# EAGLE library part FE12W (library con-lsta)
FEMALE HEADER
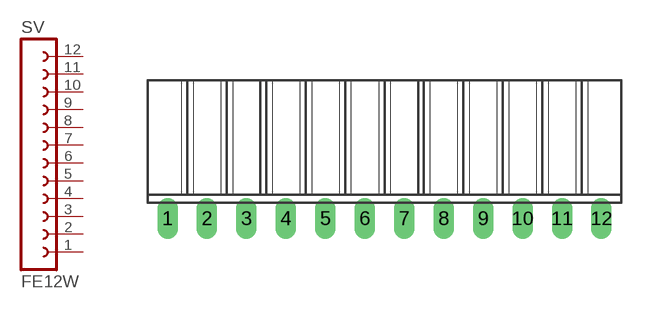
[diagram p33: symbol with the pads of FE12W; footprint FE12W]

Designator prefix SV

## FE12W (OC_FARNELL: unknown; OC_NEWARK: unknown)  [FE12W]
1  1  pas
2  2  pas
3  3  pas
4  4  pas
5  5  pas
6  6  pas
7  7  pas
8  8  pas
9  9  pas
10  10  pas
11  11  pas
12  12  pas

## Footprint FE12W (pad centres in mm)
FEMALE HEADER
drill 0.813 long: 1 -13.97,0; 2 -11.43,0; 3 -8.89,0; 4 -6.35,0; 5 -3.81,0; 6 -1.27,0; 7 1.27,0; 8 3.81,0; 9 6.35,0; 10 8.89,0; 11 11.43,0; 12 13.97,0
